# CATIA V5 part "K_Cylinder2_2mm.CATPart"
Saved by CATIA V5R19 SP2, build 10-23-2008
Part number: Cylinder2
Bounding box of the stored display mesh (mm): x 0 to 2, y -0.5 to 0.5, z -0.5 to 0.5
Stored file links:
  G:\Khaled_CFAO_2011\ST2M\ST2M_GR1\bgaltie\bgaltie\Khaled\CAD_thinkMOTION\K_Cylinder2_2mm.CATPart
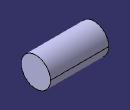
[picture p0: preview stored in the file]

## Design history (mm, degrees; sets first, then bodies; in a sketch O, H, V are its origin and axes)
AxisSystem1: origin (0, 0, 0), X (1, 0, 0), Y (0, 1, 0), Z (0, 0, 1)
Body1 (main body)
  Sketch1 on YZ plane of AxisSystem1, origin (0, 0, 0), H (0, 1, 0), V (0, 0, 1)
    circle A1 centre (0, 0) radius 0.5
    radius A1 = 0.5
  Pad1: profile Sketch1, direction (1, 0, 0), length 2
